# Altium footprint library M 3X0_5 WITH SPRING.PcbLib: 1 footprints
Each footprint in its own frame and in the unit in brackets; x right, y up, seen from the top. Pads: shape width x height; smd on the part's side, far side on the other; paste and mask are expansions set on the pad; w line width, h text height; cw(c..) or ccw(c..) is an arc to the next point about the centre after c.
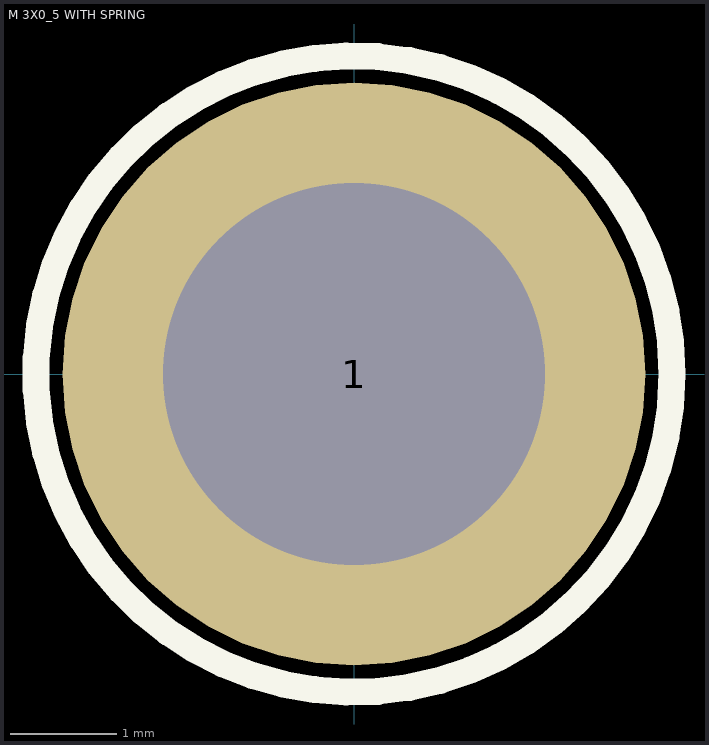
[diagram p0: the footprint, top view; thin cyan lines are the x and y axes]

## M 3X0_5 WITH SPRING [mm] "M 3X0.5 SCREW WITH ATS-PPS-06 SPRING"
height 2.4
pads (1):
  round 5.5 hole 3.6: 1(0,0)
Top Overlay:
  circle w0.254: c0,0 r3
M5 Assembly Top:
  text ".Designator" at -0.1,-0.1 h1.02
3D body: height 2.5, standoff 0, extent -3.146,-3.1 3.1,3.1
